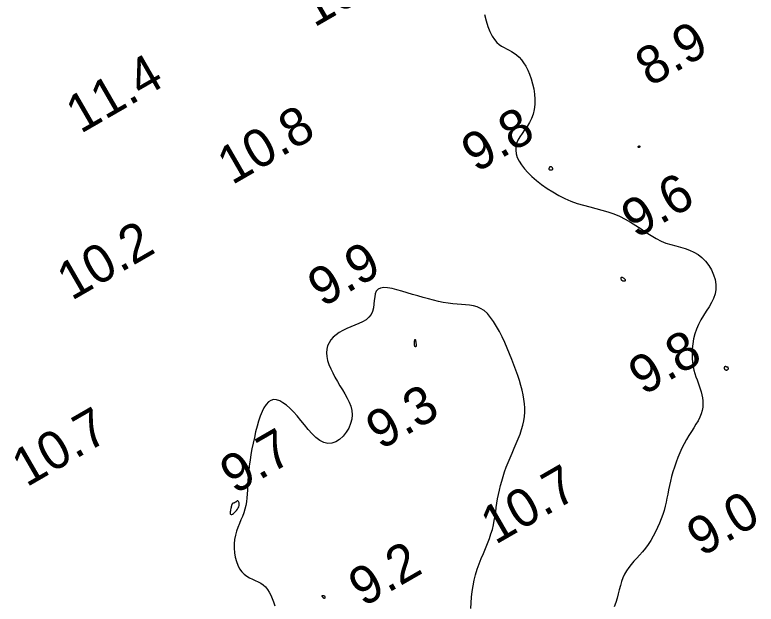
# Model space of a CAD drawing. Extents: x 3024098 to 3056816, y 418252 to 509144.
# Drawn here: x 3036712 to 3036809.6, y 419561.2 to 419638.9 of the extents above; entities that cross this region are included whole.
import ezdxf

# ---------------------------------------------------------------- set-up
doc = ezdxf.new("R2010")
doc.units = 0
doc.layers.add('V-CHAN-CONT-EL10', color=7, linetype='Continuous')
doc.layers.add('V-TOPO-SOUN-0911', color=7, linetype='Continuous')

msp = doc.modelspace()

# ---------------------------------------------------------------- linework, layer by layer
at = {"layer": 'V-CHAN-CONT-EL10'}
for points in [[(3036773.861, 419638.957), (3036774.055, 419638.155), (3036774.291, 419637.4), (3036774.559, 419636.717), (3036774.847, 419636.132), (3036775.147, 419635.662), (3036775.456, 419635.296), (3036775.772, 419635.012), (3036776.094, 419634.79), (3036776.421, 419634.609), (3036776.751, 419634.449), (3036777.083, 419634.29), (3036777.416, 419634.111), (3036777.747, 419633.894), (3036778.075, 419633.635), (3036778.396, 419633.332), (3036778.707, 419632.983), (3036779.004, 419632.587), (3036779.286, 419632.141), (3036779.549, 419631.644), (3036779.79, 419631.094), (3036780.004, 419630.492), (3036780.188, 419629.848), (3036780.332, 419629.176), (3036780.433, 419628.487), (3036780.481, 419627.796), (3036780.473, 419627.116), (3036780.4, 419626.458), (3036780.256, 419625.836), (3036780.039, 419625.26), (3036779.765, 419624.725), (3036779.456, 419624.225), (3036779.13, 419623.752), (3036778.809, 419623.298), (3036778.513, 419622.857), (3036778.262, 419622.421), (3036778.077, 419621.982), (3036777.975, 419621.534), (3036777.959, 419621.077), (3036778.026, 419620.611), (3036778.175, 419620.134), (3036778.405, 419619.647), (3036778.715, 419619.151), (3036779.103, 419618.644), (3036779.568, 419618.127), (3036780.107, 419617.602), (3036780.712, 419617.075), (3036781.376, 419616.556), (3036782.087, 419616.053), (3036782.839, 419615.574), (3036783.621, 419615.129), (3036784.425, 419614.726), (3036785.241, 419614.374), (3036786.063, 419614.077), (3036786.885, 419613.824), (3036787.704, 419613.601), (3036788.517, 419613.391), (3036789.32, 419613.178), (3036790.111, 419612.949), (3036790.886, 419612.687), (3036791.641, 419612.377), (3036792.375, 419612.009), (3036793.089, 419611.595), (3036793.786, 419611.152), (3036794.468, 419610.697), (3036795.139, 419610.248), (3036795.8, 419609.821), (3036796.455, 419609.434), (3036797.106, 419609.104), (3036797.756, 419608.843), (3036798.401, 419608.634), (3036799.037, 419608.458), (3036799.663, 419608.294), (3036800.272, 419608.121), (3036800.863, 419607.919), (3036801.432, 419607.665), (3036801.975, 419607.34), (3036802.486, 419606.928), (3036802.958, 419606.44), (3036803.378, 419605.89), (3036803.736, 419605.293), (3036804.021, 419604.664), (3036804.223, 419604.02), (3036804.331, 419603.375), (3036804.334, 419602.744), (3036804.226, 419602.139), (3036804.024, 419601.556), (3036803.749, 419600.989), (3036803.423, 419600.429), (3036803.067, 419599.87), (3036802.702, 419599.305), (3036802.351, 419598.726), (3036802.035, 419598.126), (3036801.771, 419597.501), (3036801.56, 419596.857), (3036801.4, 419596.202), (3036801.287, 419595.548), (3036801.218, 419594.902), (3036801.19, 419594.273), (3036801.201, 419593.672), (3036801.247, 419593.106), (3036801.325, 419592.584), (3036801.43, 419592.1), (3036801.554, 419591.649), (3036801.693, 419591.223), (3036801.841, 419590.817), (3036801.991, 419590.423), (3036802.137, 419590.035), (3036802.273, 419589.648), (3036802.395, 419589.254), (3036802.495, 419588.854), (3036802.57, 419588.447), (3036802.614, 419588.035), (3036802.622, 419587.616), (3036802.59, 419587.191), (3036802.512, 419586.76), (3036802.383, 419586.324), (3036802.201, 419585.882), (3036801.972, 419585.432), (3036801.706, 419584.971), (3036801.412, 419584.496), (3036801.1, 419584.004), (3036800.778, 419583.492), (3036800.457, 419582.958), (3036800.145, 419582.398), (3036799.85, 419581.812), (3036799.575, 419581.204), (3036799.319, 419580.581), (3036799.083, 419579.948), (3036798.867, 419579.314), (3036798.671, 419578.683), (3036798.497, 419578.063), (3036798.344, 419577.46), (3036798.211, 419576.878), (3036798.093, 419576.315), (3036797.984, 419575.766), (3036797.877, 419575.225), (3036797.764, 419574.689), (3036797.64, 419574.152), (3036797.497, 419573.609), (3036797.329, 419573.055), (3036797.131, 419572.488), (3036796.903, 419571.912), (3036796.648, 419571.333), (3036796.367, 419570.758), (3036796.064, 419570.193), (3036795.74, 419569.644), (3036795.397, 419569.118), (3036795.038, 419568.622), (3036794.665, 419568.158), (3036794.286, 419567.722), (3036793.907, 419567.305), (3036793.537, 419566.898), (3036793.184, 419566.493), (3036792.854, 419566.082), (3036792.555, 419565.656), (3036792.296, 419565.207), (3036792.08, 419564.728), (3036791.899, 419564.223), (3036791.743, 419563.695), (3036791.599, 419563.15), (3036791.457, 419562.592), (3036791.306, 419562.027), (3036791.134, 419561.458), (3036790.93, 419560.891)], [(3036772.054, 419560.668), (3036772.087, 419561.421), (3036772.146, 419562.173), (3036772.232, 419562.921), (3036772.348, 419563.664), (3036772.498, 419564.4), (3036772.684, 419565.127), (3036772.905, 419565.844), (3036773.156, 419566.549), (3036773.425, 419567.243), (3036773.703, 419567.923), (3036773.98, 419568.59), (3036774.246, 419569.242), (3036774.491, 419569.88), (3036774.706, 419570.502), (3036774.883, 419571.109), (3036775.027, 419571.702), (3036775.144, 419572.285), (3036775.242, 419572.859), (3036775.328, 419573.429), (3036775.409, 419573.996), (3036775.492, 419574.563), (3036775.584, 419575.134), (3036775.692, 419575.711), (3036775.816, 419576.293), (3036775.958, 419576.882), (3036776.118, 419577.477), (3036776.297, 419578.078), (3036776.496, 419578.684), (3036776.715, 419579.297), (3036776.955, 419579.916), (3036777.215, 419580.541), (3036777.487, 419581.168), (3036777.764, 419581.797), (3036778.037, 419582.423), (3036778.297, 419583.044), (3036778.536, 419583.658), (3036778.745, 419584.261), (3036778.915, 419584.851), (3036779.04, 419585.427), (3036779.121, 419585.992), (3036779.159, 419586.551), (3036779.157, 419587.11), (3036779.118, 419587.673), (3036779.044, 419588.246), (3036778.937, 419588.833), (3036778.801, 419589.44), (3036778.637, 419590.071), (3036778.446, 419590.723), (3036778.231, 419591.396), (3036777.994, 419592.087), (3036777.735, 419592.794), (3036777.457, 419593.513), (3036777.16, 419594.244), (3036776.847, 419594.983), (3036776.52, 419595.727), (3036776.177, 419596.463), (3036775.819, 419597.177), (3036775.445, 419597.856), (3036775.056, 419598.486), (3036774.652, 419599.052), (3036774.231, 419599.541), (3036773.795, 419599.939), (3036773.342, 419600.237), (3036772.872, 419600.447), (3036772.385, 419600.586), (3036771.879, 419600.672), (3036771.355, 419600.723), (3036770.811, 419600.754), (3036770.247, 419600.784), (3036769.661, 419600.83), (3036769.055, 419600.905), (3036768.429, 419601.01), (3036767.786, 419601.142), (3036767.127, 419601.297), (3036766.454, 419601.471), (3036765.769, 419601.662), (3036765.076, 419601.866), (3036764.374, 419602.08), (3036763.669, 419602.299), (3036762.973, 419602.509), (3036762.302, 419602.696), (3036761.669, 419602.845), (3036761.09, 419602.941), (3036760.579, 419602.97), (3036760.152, 419602.916), (3036759.824, 419602.764), (3036759.601, 419602.507), (3036759.464, 419602.159), (3036759.385, 419601.743), (3036759.338, 419601.281), (3036759.295, 419600.796), (3036759.229, 419600.309), (3036759.113, 419599.842), (3036758.918, 419599.419), (3036758.627, 419599.054), (3036758.249, 419598.743), (3036757.802, 419598.473), (3036757.307, 419598.232), (3036756.78, 419598.009), (3036756.241, 419597.793), (3036755.707, 419597.57), (3036755.198, 419597.331), (3036754.729, 419597.064), (3036754.308, 419596.768), (3036753.939, 419596.442), (3036753.627, 419596.088), (3036753.377, 419595.706), (3036753.193, 419595.294), (3036753.08, 419594.854), (3036753.042, 419594.386), (3036753.083, 419593.89), (3036753.194, 419593.371), (3036753.367, 419592.833), (3036753.591, 419592.282), (3036753.857, 419591.722), (3036754.155, 419591.158), (3036754.477, 419590.595), (3036754.811, 419590.038), (3036755.148, 419589.49), (3036755.474, 419588.949), (3036755.774, 419588.412), (3036756.034, 419587.873), (3036756.239, 419587.331), (3036756.375, 419586.78), (3036756.426, 419586.217), (3036756.378, 419585.638), (3036756.221, 419585.045), (3036755.966, 419584.456), (3036755.628, 419583.897), (3036755.221, 419583.393), (3036754.76, 419582.968), (3036754.261, 419582.647), (3036753.739, 419582.454), (3036753.208, 419582.415), (3036752.682, 419582.544), (3036752.162, 419582.823), (3036751.648, 419583.223), (3036751.141, 419583.716), (3036750.639, 419584.274), (3036750.142, 419584.867), (3036749.651, 419585.468), (3036749.165, 419586.049), (3036748.685, 419586.584), (3036748.212, 419587.059), (3036747.751, 419587.466), (3036747.304, 419587.793), (3036746.874, 419588.031), (3036746.464, 419588.171), (3036746.078, 419588.201), (3036745.718, 419588.112), (3036745.387, 419587.898), (3036745.084, 419587.569), (3036744.805, 419587.139), (3036744.55, 419586.622), (3036744.315, 419586.031), (3036744.098, 419585.382), (3036743.898, 419584.688), (3036743.711, 419583.963), (3036743.537, 419583.219), (3036743.375, 419582.465), (3036743.227, 419581.708), (3036743.094, 419580.955), (3036742.977, 419580.212), (3036742.877, 419579.486), (3036742.794, 419578.785), (3036742.731, 419578.114), (3036742.687, 419577.48), (3036742.655, 419576.879), (3036742.628, 419576.308), (3036742.599, 419575.764), (3036742.559, 419575.241), (3036742.502, 419574.736), (3036742.419, 419574.246), (3036742.302, 419573.766), (3036742.149, 419573.291), (3036741.967, 419572.819), (3036741.767, 419572.345), (3036741.563, 419571.863), (3036741.366, 419571.371), (3036741.186, 419570.863), (3036741.038, 419570.336), (3036740.932, 419569.785), (3036740.877, 419569.209), (3036740.875, 419568.618), (3036740.924, 419568.025), (3036741.022, 419567.445), (3036741.167, 419566.89), (3036741.358, 419566.374), (3036741.593, 419565.91), (3036741.871, 419565.511), (3036742.187, 419565.187), (3036742.535, 419564.926), (3036742.903, 419564.712), (3036743.282, 419564.528), (3036743.663, 419564.359), (3036744.034, 419564.188), (3036744.386, 419564), (3036744.71, 419563.778), (3036744.997, 419563.509), (3036745.252, 419563.194), (3036745.48, 419562.836), (3036745.688, 419562.437), (3036745.88, 419562.003), (3036746.063, 419561.535), (3036746.243, 419561.038)]]:
    msp.add_lwpolyline(points, dxfattribs=at)
for points in [[(3036794.159, 419621.431), (3036794.144, 419621.435), (3036794.131, 419621.442), (3036794.12, 419621.451), (3036794.11, 419621.462), (3036794.102, 419621.475), (3036794.097, 419621.489), (3036794.094, 419621.505), (3036794.094, 419621.52), (3036794.096, 419621.537), (3036794.101, 419621.553), (3036794.107, 419621.568), (3036794.115, 419621.583), (3036794.125, 419621.597), (3036794.136, 419621.609), (3036794.147, 419621.619), (3036794.16, 419621.627), (3036794.172, 419621.633), (3036794.185, 419621.637), (3036794.198, 419621.64), (3036794.21, 419621.641), (3036794.222, 419621.642), (3036794.234, 419621.641), (3036794.244, 419621.64), (3036794.253, 419621.638), (3036794.262, 419621.636), (3036794.269, 419621.633), (3036794.276, 419621.63), (3036794.282, 419621.625), (3036794.287, 419621.62), (3036794.292, 419621.613), (3036794.297, 419621.605), (3036794.302, 419621.596), (3036794.306, 419621.586), (3036794.31, 419621.576), (3036794.313, 419621.565), (3036794.316, 419621.555), (3036794.319, 419621.545), (3036794.321, 419621.535), (3036794.322, 419621.528), (3036794.323, 419621.521), (3036794.322, 419621.516), (3036794.321, 419621.512), (3036794.318, 419621.508), (3036794.314, 419621.504), (3036794.309, 419621.5), (3036794.302, 419621.495), (3036794.293, 419621.488), (3036794.281, 419621.48), (3036794.268, 419621.471), (3036794.254, 419621.462), (3036794.239, 419621.452), (3036794.223, 419621.444), (3036794.206, 419621.437), (3036794.19, 419621.432), (3036794.174, 419621.429)], [(3036782.732, 419618.467), (3036782.681, 419618.454), (3036782.624, 419618.445), (3036782.565, 419618.442), (3036782.507, 419618.446), (3036782.453, 419618.457), (3036782.407, 419618.476), (3036782.373, 419618.503), (3036782.353, 419618.538), (3036782.346, 419618.58), (3036782.349, 419618.627), (3036782.361, 419618.677), (3036782.379, 419618.727), (3036782.4, 419618.776), (3036782.423, 419618.821), (3036782.445, 419618.86), (3036782.465, 419618.892), (3036782.482, 419618.917), (3036782.497, 419618.936), (3036782.511, 419618.948), (3036782.524, 419618.956), (3036782.537, 419618.959), (3036782.551, 419618.958), (3036782.566, 419618.955), (3036782.582, 419618.949), (3036782.599, 419618.941), (3036782.617, 419618.931), (3036782.636, 419618.92), (3036782.654, 419618.907), (3036782.672, 419618.893), (3036782.689, 419618.879), (3036782.705, 419618.864), (3036782.719, 419618.849), (3036782.731, 419618.834), (3036782.742, 419618.817), (3036782.753, 419618.8), (3036782.763, 419618.781), (3036782.773, 419618.76), (3036782.784, 419618.738), (3036782.795, 419618.712), (3036782.807, 419618.685), (3036782.819, 419618.655), (3036782.827, 419618.624), (3036782.832, 419618.594), (3036782.831, 419618.564), (3036782.822, 419618.535), (3036782.804, 419618.509), (3036782.774, 419618.486)], [(3036792.355, 419604.088), (3036792.302, 419604.136), (3036792.239, 419604.183), (3036792.171, 419604.227), (3036792.101, 419604.265), (3036792.032, 419604.295), (3036791.968, 419604.313), (3036791.912, 419604.318), (3036791.869, 419604.308), (3036791.837, 419604.284), (3036791.817, 419604.25), (3036791.807, 419604.207), (3036791.808, 419604.16), (3036791.818, 419604.11), (3036791.837, 419604.06), (3036791.865, 419604.014), (3036791.901, 419603.973), (3036791.943, 419603.938), (3036791.99, 419603.908), (3036792.041, 419603.885), (3036792.094, 419603.867), (3036792.148, 419603.856), (3036792.201, 419603.85), (3036792.252, 419603.849), (3036792.3, 419603.855), (3036792.342, 419603.866), (3036792.378, 419603.883), (3036792.405, 419603.905), (3036792.422, 419603.932), (3036792.427, 419603.964), (3036792.418, 419604.001), (3036792.394, 419604.042)], [(3036764.743, 419596.083), (3036764.759, 419596.017), (3036764.775, 419595.936), (3036764.791, 419595.843), (3036764.806, 419595.746), (3036764.82, 419595.648), (3036764.833, 419595.557), (3036764.844, 419595.477), (3036764.852, 419595.413), (3036764.859, 419595.363), (3036764.863, 419595.326), (3036764.866, 419595.298), (3036764.866, 419595.279), (3036764.863, 419595.264), (3036764.858, 419595.253), (3036764.851, 419595.243), (3036764.841, 419595.231), (3036764.829, 419595.219), (3036764.815, 419595.207), (3036764.8, 419595.195), (3036764.785, 419595.185), (3036764.769, 419595.177), (3036764.753, 419595.172), (3036764.738, 419595.171), (3036764.724, 419595.173), (3036764.71, 419595.181), (3036764.698, 419595.193), (3036764.687, 419595.21), (3036764.676, 419595.232), (3036764.667, 419595.26), (3036764.658, 419595.293), (3036764.651, 419595.332), (3036764.644, 419595.377), (3036764.638, 419595.427), (3036764.634, 419595.482), (3036764.631, 419595.541), (3036764.629, 419595.604), (3036764.63, 419595.671), (3036764.632, 419595.74), (3036764.635, 419595.81), (3036764.641, 419595.882), (3036764.649, 419595.952), (3036764.659, 419596.017), (3036764.67, 419596.072), (3036764.683, 419596.114), (3036764.696, 419596.139), (3036764.711, 419596.145), (3036764.726, 419596.127)], [(3036805.692, 419592.066), (3036805.66, 419592.074), (3036805.626, 419592.087), (3036805.593, 419592.105), (3036805.56, 419592.129), (3036805.531, 419592.158), (3036805.506, 419592.193), (3036805.486, 419592.234), (3036805.472, 419592.282), (3036805.466, 419592.333), (3036805.465, 419592.386), (3036805.47, 419592.438), (3036805.481, 419592.486), (3036805.496, 419592.529), (3036805.516, 419592.563), (3036805.539, 419592.587), (3036805.567, 419592.598), (3036805.597, 419592.599), (3036805.628, 419592.591), (3036805.661, 419592.578), (3036805.693, 419592.563), (3036805.724, 419592.546), (3036805.753, 419592.533), (3036805.779, 419592.524), (3036805.802, 419592.522), (3036805.821, 419592.525), (3036805.837, 419592.531), (3036805.851, 419592.538), (3036805.862, 419592.544), (3036805.873, 419592.546), (3036805.882, 419592.543), (3036805.89, 419592.531), (3036805.899, 419592.511), (3036805.907, 419592.482), (3036805.914, 419592.447), (3036805.921, 419592.408), (3036805.926, 419592.367), (3036805.929, 419592.327), (3036805.93, 419592.289), (3036805.928, 419592.255), (3036805.924, 419592.227), (3036805.918, 419592.204), (3036805.909, 419592.186), (3036805.899, 419592.172), (3036805.888, 419592.16), (3036805.876, 419592.149), (3036805.864, 419592.139), (3036805.851, 419592.129), (3036805.84, 419592.118), (3036805.828, 419592.106), (3036805.815, 419592.094), (3036805.801, 419592.083), (3036805.786, 419592.074), (3036805.767, 419592.067), (3036805.746, 419592.063), (3036805.721, 419592.062)], [(3036741.486, 419574.083), (3036741.528, 419574.234), (3036741.548, 419574.375), (3036741.548, 419574.503), (3036741.533, 419574.616), (3036741.506, 419574.712), (3036741.469, 419574.786), (3036741.427, 419574.838), (3036741.382, 419574.864), (3036741.335, 419574.869), (3036741.286, 419574.856), (3036741.236, 419574.829), (3036741.185, 419574.794), (3036741.132, 419574.753), (3036741.079, 419574.712), (3036741.025, 419574.674), (3036740.972, 419574.643), (3036740.918, 419574.618), (3036740.866, 419574.597), (3036740.816, 419574.579), (3036740.769, 419574.562), (3036740.725, 419574.545), (3036740.686, 419574.525), (3036740.651, 419574.503), (3036740.622, 419574.475), (3036740.598, 419574.44), (3036740.576, 419574.396), (3036740.556, 419574.342), (3036740.537, 419574.275), (3036740.517, 419574.193), (3036740.494, 419574.095), (3036740.468, 419573.979), (3036740.437, 419573.844), (3036740.406, 419573.698), (3036740.38, 419573.549), (3036740.361, 419573.405), (3036740.356, 419573.276), (3036740.368, 419573.168), (3036740.403, 419573.092), (3036740.463, 419573.056), (3036740.553, 419573.065), (3036740.667, 419573.116), (3036740.796, 419573.202), (3036740.934, 419573.316), (3036741.072, 419573.452), (3036741.204, 419573.603), (3036741.321, 419573.763), (3036741.417, 419573.925)], [(3036752.665, 419562.039), (3036752.656, 419562.046), (3036752.648, 419562.053), (3036752.642, 419562.058), (3036752.637, 419562.064), (3036752.632, 419562.068), (3036752.629, 419562.073), (3036752.625, 419562.077), (3036752.622, 419562.08), (3036752.618, 419562.084), (3036752.614, 419562.089), (3036752.609, 419562.096), (3036752.602, 419562.104), (3036752.592, 419562.115), (3036752.58, 419562.13), (3036752.565, 419562.148), (3036752.547, 419562.171), (3036752.527, 419562.197), (3036752.507, 419562.226), (3036752.488, 419562.255), (3036752.472, 419562.284), (3036752.46, 419562.311), (3036752.456, 419562.336), (3036752.459, 419562.357), (3036752.472, 419562.372), (3036752.492, 419562.383), (3036752.519, 419562.39), (3036752.55, 419562.392), (3036752.585, 419562.391), (3036752.62, 419562.387), (3036752.655, 419562.38), (3036752.688, 419562.371), (3036752.716, 419562.359), (3036752.741, 419562.346), (3036752.763, 419562.33), (3036752.781, 419562.313), (3036752.795, 419562.293), (3036752.807, 419562.271), (3036752.815, 419562.246), (3036752.821, 419562.22), (3036752.824, 419562.191), (3036752.825, 419562.161), (3036752.823, 419562.131), (3036752.819, 419562.102), (3036752.813, 419562.074), (3036752.806, 419562.05), (3036752.796, 419562.029), (3036752.785, 419562.013), (3036752.772, 419562.003), (3036752.758, 419561.999), (3036752.744, 419561.998), (3036752.729, 419562.001), (3036752.714, 419562.007), (3036752.7, 419562.014), (3036752.687, 419562.023), (3036752.675, 419562.031)]]:
    msp.add_lwpolyline(points, close=True, dxfattribs=at)

# ---------------------------------------------------------------- texts
at = {"layer": 'V-TOPO-SOUN-0911'}
for s, p in [('10.4 ', (3036751.417, 419637.211)), ('8.9', (3036795.647, 419629.381)), ('11.4 ', (3036720.647, 419623.201)), ('10.8 ', (3036740.597, 419616.441)), ('9.8', (3036772.747, 419618.061)), ('9.6', (3036793.805, 419609.372)), ('10.2 ', (3036719.467, 419601.191)), ('9.9', (3036752.507, 419600.311)), ('9.8', (3036794.757, 419588.691)), ('9.3', (3036760.177, 419581.511)), ('10.7 ', (3036713.527, 419576.611)), ('9.7', (3036740.957, 419575.671)), ('10.7 ', (3036775.277, 419569.031)), ('9.0', (3036802.435, 419567.431)), ('9.2', (3036757.887, 419560.811))]:
    msp.add_text(s, height=5, rotation=30, dxfattribs=at).set_placement(p)

doc.saveas('drawing.dxf')
